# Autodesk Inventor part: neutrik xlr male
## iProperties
Created: 2011-01
Part Number: neutrik xlr male
Document SubType Name: Modeling
Designer: eric
Density: 1 g/cm^3
Mass: 3.83446 g
Surface Area: 38.8213 cm^2
Volume: 3.83446 cm^3
Author: eric
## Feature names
1. Base1
